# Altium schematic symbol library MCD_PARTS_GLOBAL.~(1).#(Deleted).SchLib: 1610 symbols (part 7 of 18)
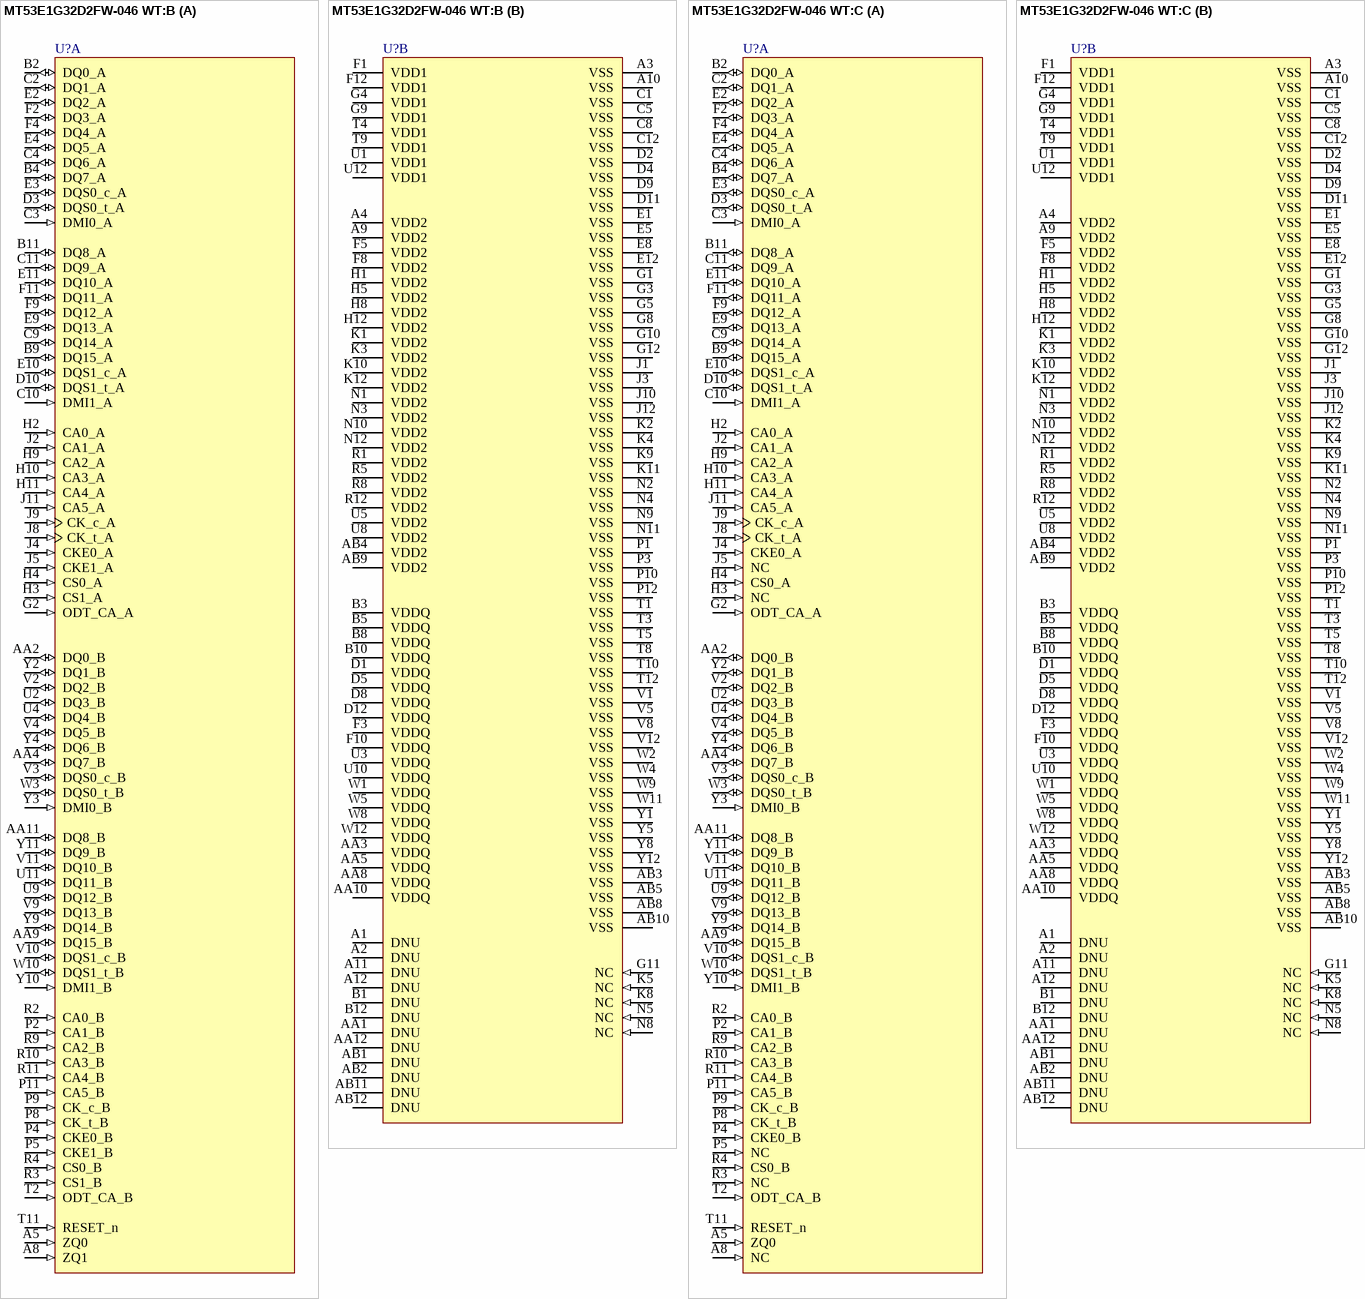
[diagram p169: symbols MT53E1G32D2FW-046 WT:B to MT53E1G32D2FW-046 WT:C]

## MT53E1G32D2FW-046 WT:C
designator U?
part A pins: A5 ZQ0 (in) "External impedance (240 ohm): This signal is used to calibrate the device output impedance.", A8 NC (in), AA2 DQ0_B (io) "Data input/output: Bidirectional data bus.", AA4 DQ7_B (io) "Data input/output: Bidirectional data bus.", AA9 DQ15_B (io) "Data input/output: Bidirectional data bus.", AA11 DQ8_B (io) "Data input/output: Bidirectional data bus.", B2 DQ0_A (io) "Data input/output: Bidirectional data bus.", B4 DQ7_A (io) "Data input/output: Bidirectional data bus.", B9 DQ15_A (io) "Data input/output: Bidirectional data bus.", B11 DQ8_A (io) "Data input/output: Bidirectional data bus.", C2 DQ1_A (io) "Data input/output: Bidirectional data bus.", C3 DMI0_A (in) "Input data mask: DM is an input mask signal for write data. Although DM ballsare input-only, the DM loading is designed to match that of DQ and DQS balls.DM[3:0] is DM for each of the four data bytes, respectively.", C4 DQ6_A (io) "Data input/output: Bidirectional data bus.", C9 DQ14_A (io) "Data input/output: Bidirectional data bus.", C10 DMI1_A (in) "Input data mask: DM is an input mask signal for write data. Although DM ballsare input-only, the DM loading is designed to match that of DQ and DQS balls.DM[3:0] is DM for each of the four data bytes, respectively.", C11 DQ9_A (io) "Data input/output: Bidirectional data bus.", D3 DQS0_t_A (io) "Data strobe: The data strobe is bidirectional (used for read and write data) andcomplementary (DQS and DQS#). It is edge-aligned output with read data andcentered input with write data. DQS[3:0]/DQS[3:0]# is DQS for each of (See Datasheet)", D10 DQS1_t_A (io) "Data strobe: The data strobe is bidirectional (used for read and write data) andcomplementary (DQS and DQS#). It is edge-aligned output with read data andcentered input with write data. DQS[3:0]/DQS[3:0]# is DQS for each of (See Datasheet)", E2 DQ2_A (io) "Data input/output: Bidirectional data bus.", E3 DQS0_c_A (io) "Data strobe: The data strobe is bidirectional (used for read and write data) andcomplementary (DQS and DQS#). It is edge-aligned output with read data andcentered input with write data. DQS[3:0]/DQS[3:0]# is DQS for each of (See Datasheet)", E4 DQ5_A (io) "Data input/output: Bidirectional data bus.", E9 DQ13_A (io) "Data input/output: Bidirectional data bus.", E10 DQS1_c_A (io) "Data strobe: The data strobe is bidirectional (used for read and write data) andcomplementary (DQS and DQS#). It is edge-aligned output with read data andcentered input with write data. DQS[3:0]/DQS[3:0]# is DQS for each of (See Datasheet)", E11 DQ10_A (io) "Data input/output: Bidirectional data bus.", F2 DQ3_A (io) "Data input/output: Bidirectional data bus.", F4 DQ4_A (io) "Data input/output: Bidirectional data bus.", F9 DQ12_A (io) "Data input/output: Bidirectional data bus.", F11 DQ11_A (io) "Data input/output: Bidirectional data bus.", G2 ODT_CA_A (in) "on die termination on CA", H2 CA0_A (in) "Command/address inputs: Provide the command and address inputs accordingto the command truth table.", H3 NC (in), H4 CS0_A (in) "Chip select: CS# is considered part of the command code and is sampled at therising edge of CK.", H9 CA2_A (in) "Command/address inputs: Provide the command and address inputs accordingto the command truth table.", H10 CA3_A (in) "Command/address inputs: Provide the command and address inputs accordingto the command truth table.", H11 CA4_A (in) "Command/address inputs: Provide the command and address inputs accordingto the command truth table.", J2 CA1_A (in) "Command/address inputs: Provide the command and address inputs accordingto the command truth table.", J4 CKE0_A (in) "Clock enable: CKE HIGH activates and CKE LOW deactivates the internal clocksignals, input buffers, and output drivers. Power-saving modes are entered andexited via CKE transitions. CKE is considered part of the command code. (See Datasheet)", J5 NC (in), J8 CK_t_A (in) "Clock: CK and CK# are differential clock inputs. All CA inputs are sampled onboth rising and falling edges of CK. CS and CKE inputs are sampled at the risingedge of CK. AC timings are referenced to clock.", J9 CK_c_A (in) "Clock: CK and CK# are differential clock inputs. All CA inputs are sampled onboth rising and falling edges of CK. CS and CKE inputs are sampled at the risingedge of CK. AC timings are referenced to clock.", J11 CA5_A (in) "Command/address inputs: Provide the command and address inputs accordingto the command truth table.", P2 CA1_B (in) "Command/address inputs: Provide the command and address inputs accordingto the command truth table.", P4 CKE0_B (in) "Clock enable: CKE HIGH activates and CKE LOW deactivates the internal clocksignals, input buffers, and output drivers. Power-saving modes are entered andexited via CKE transitions. CKE is considered part of the command code. (See Datasheet)", P5 NC (in), P8 CK_t_B (in) "Clock: CK and CK# are differential clock inputs. All CA inputs are sampled onboth rising and falling edges of CK. CS and CKE inputs are sampled at the risingedge of CK. AC timings are referenced to clock.", P9 CK_c_B (in) "Clock: CK and CK# are differential clock inputs. All CA inputs are sampled onboth rising and falling edges of CK. CS and CKE inputs are sampled at the risingedge of CK. AC timings are referenced to clock.", P11 CA5_B (in) "Command/address inputs: Provide the command and address inputs accordingto the command truth table.", R2 CA0_B (in) "Command/address inputs: Provide the command and address inputs accordingto the command truth table.", R3 NC (in), R4 CS0_B (in) "Chip select: CS# is considered part of the command code and is sampled at therising edge of CK.", R9 CA2_B (in) "Command/address inputs: Provide the command and address inputs accordingto the command truth table.", R10 CA3_B (in) "Command/address inputs: Provide the command and address inputs accordingto the command truth table.", R11 CA4_B (in) "Command/address inputs: Provide the command and address inputs accordingto the command truth table.", T2 ODT_CA_B (in) "on die termination on CA", T11 RESET_n (in) "Reset active low", U2 DQ3_B (io) "Data input/output: Bidirectional data bus.", U4 DQ4_B (io) "Data input/output: Bidirectional data bus.", U9 DQ12_B (io) "Data input/output: Bidirectional data bus.", U11 DQ11_B (io) "Data input/output: Bidirectional data bus.", V2 DQ2_B (io) "Data input/output: Bidirectional data bus.", V3 DQS0_c_B (io) "Data strobe: The data strobe is bidirectional (used for read and write data) andcomplementary (DQS and DQS#). It is edge-aligned output with read data andcentered input with write data. DQS[3:0]/DQS[3:0]# is DQS for each of (See Datasheet)", V4 DQ5_B (io) "Data input/output: Bidirectional data bus.", V9 DQ13_B (io) "Data input/output: Bidirectional data bus.", V10 DQS1_c_B (io) "Data strobe: The data strobe is bidirectional (used for read and write data) andcomplementary (DQS and DQS#). It is edge-aligned output with read data andcentered input with write data. DQS[3:0]/DQS[3:0]# is DQS for each of (See Datasheet)", V11 DQ10_B (io) "Data input/output: Bidirectional data bus.", W3 DQS0_t_B (io) "Data strobe: The data strobe is bidirectional (used for read and write data) andcomplementary (DQS and DQS#). It is edge-aligned output with read data andcentered input with write data. DQS[3:0]/DQS[3:0]# is DQS for each of (See Datasheet)", W10 DQS1_t_B (io) "Data strobe: The data strobe is bidirectional (used for read and write data) andcomplementary (DQS and DQS#). It is edge-aligned output with read data andcentered input with write data. DQS[3:0]/DQS[3:0]# is DQS for each of (See Datasheet)", Y2 DQ1_B (io) "Data input/output: Bidirectional data bus.", Y3 DMI0_B (in) "Input data mask: DM is an input mask signal for write data. Although DM ballsare input-only, the DM loading is designed to match that of DQ and DQS balls.DM[3:0] is DM for each of the four data bytes, respectively.", Y4 DQ6_B (io) "Data input/output: Bidirectional data bus.", Y9 DQ14_B (io) "Data input/output: Bidirectional data bus.", Y10 DMI1_B (in) "Input data mask: DM is an input mask signal for write data. Although DM ballsare input-only, the DM loading is designed to match that of DQ and DQS balls.DM[3:0] is DM for each of the four data bytes, respectively.", Y11 DQ9_B (io) "Data input/output: Bidirectional data bus."
part B pins: A1 DNU "Do not use: Must be grounded or left floating.", A2 DNU "Do not use: Must be grounded or left floating.", A3 VSS (power) "Common ground.", A4 VDD2 (power) "Core power: Supply 2.", A9 VDD2 (power) "Core power: Supply 2.", A10 VSS (power) "Common ground.", A11 DNU "Do not use: Must be grounded or left floating.", A12 DNU "Do not use: Must be grounded or left floating.", AA1 DNU "Do not use: Must be grounded or left floating.", AA3 VDDQ (power) "DQ power supply: Isolated on the die for improved noise immunity.", AA5 VDDQ (power) "DQ power supply: Isolated on the die for improved noise immunity.", AA8 VDDQ (power) "DQ power supply: Isolated on the die for improved noise immunity.", AA10 VDDQ (power) "DQ power supply: Isolated on the die for improved noise immunity.", AA12 DNU "Do not use: Must be grounded or left floating.", AB1 DNU "Do not use: Must be grounded or left floating.", AB2 DNU "Do not use: Must be grounded or left floating.", AB3 VSS "Common ground.", AB4 VDD2 (power) "Core power: Supply 2.", AB5 VSS "Common ground.", AB8 VSS "Common ground.", AB9 VDD2 (power) "Core power: Supply 2.", AB10 VSS "Common ground.", AB11 DNU "Do not use: Must be grounded or left floating.", AB12 DNU "Do not use: Must be grounded or left floating.", B1 DNU "Do not use: Must be grounded or left floating.", B3 VDDQ (power) "DQ power supply: Isolated on the die for improved noise immunity.", B5 VDDQ (power) "DQ power supply: Isolated on the die for improved noise immunity.", B8 VDDQ (power) "DQ power supply: Isolated on the die for improved noise immunity.", B10 VDDQ (power) "DQ power supply: Isolated on the die for improved noise immunity.", B12 DNU "Do not use: Must be grounded or left floating.", C1 VSS (power) "Common ground.", C5 VSS (power) "Common ground.", C8 VSS (power) "Common ground.", C12 VSS (power) "Common ground.", D1 VDDQ (power) "DQ power supply: Isolated on the die for improved noise immunity.", D2 VSS (power) "Common ground.", D4 VSS (power) "Common ground.", D5 VDDQ (power) "DQ power supply: Isolated on the die for improved noise immunity.", D8 VDDQ (power) "DQ power supply: Isolated on the die for improved noise immunity.", D9 VSS (power) "Common ground.", D11 VSS (power) "Common ground.", D12 VDDQ (power) "DQ power supply: Isolated on the die for improved noise immunity.", E1 VSS (power) "Common ground.", E5 VSS (power) "Common ground.", E8 VSS (power) "Common ground.", E12 VSS (power) "Common ground.", F1 VDD1 (power) "Core power: Supply 1.", F3 VDDQ (power) "DQ power supply: Isolated on the die for improved noise immunity.", F5 VDD2 (power) "Core power: Supply 2.", F8 VDD2 (power) "Core power: Supply 2.", F10 VDDQ (power) "DQ power supply: Isolated on the die for improved noise immunity.", F12 VDD1 (power) "Core power: Supply 1.", G1 VSS (power) "Common ground.", G3 VSS (power) "Common ground.", G4 VDD1 (power) "Core power: Supply 1.", G5 VSS (power) "Common ground.", G8 VSS (power) "Common ground.", G9 VDD1 (power) "Core power: Supply 1.", G10 VSS (power) "Common ground.", G11 NC (in) "Not connected", G12 VSS (power) "Common ground.", H1 VDD2 (power) "Core power: Supply 2.", H5 VDD2 (power) "Core power: Supply 2.", H8 VDD2 (power) "Core power: Supply 2.", H12 VDD2 (power) "Core power: Supply 2.", J1 VSS (power) "Common ground.", J3 VSS (power) "Common ground.", J10 VSS (power) "Common ground.", J12 VSS (power) "Common ground.", K1 VDD2 (power) "Core power: Supply 2.", K2 VSS (power) "Common ground.", K3 VDD2 (power) "Core power: Supply 2.", K4 VSS (power) "Common ground.", K5 NC (in) "Not connected", K8 NC (in) "Not connected", K9 VSS (power) "Common ground.", K10 VDD2 (power) "Core power: Supply 2.", K11 VSS "Common ground.", K12 VDD2 (power) "Core power: Supply 2.", N1 VDD2 (power) "Core power: Supply 2.", N2 VSS "Common ground.", N3 VDD2 (power) "Core power: Supply 2.", N4 VSS "Common ground.", N5 NC (in) "Not connected", N8 NC (in) "Not connected", N9 VSS "Common ground.", N10 VDD2 (power) "Core power: Supply 2.", N11 VSS "Common ground.", N12 VDD2 (power) "Core power: Supply 2.", P1 VSS "Common ground.", P3 VSS (power) "Common ground.", P10 VSS (power) "Common ground.", P12 VSS "Common ground.", R1 VDD2 (power) "Core power: Supply 2.", R5 VDD2 (power) "Core power: Supply 2.", R8 VDD2 (power) "Core power: Supply 2.", R12 VDD2 (power) "Core power: Supply 2.", T1 VSS "Common ground.", T3 VSS "Common ground.", T4 VDD1 (power) "Core power: Supply 1.", T5 VSS "Common ground.", T8 VSS "Common ground.", T9 VDD1 (power) "Core power: Supply 1.", T10 VSS "Common ground.", T12 VSS "Common ground.", U1 VDD1 (power) "Core power: Supply 1.", U3 VDDQ (power) "DQ power supply: Isolated on the die for improved noise immunity.", U5 VDD2 (power) "Core power: Supply 2.", U8 VDD2 (power) "Core power: Supply 2.", U10 VDDQ (power) "DQ power supply: Isolated on the die for improved noise immunity.", U12 VDD1 (power) "Core power: Supply 1.", V1 VSS (power) "Common ground.", V5 VSS (power) "Common ground.", V8 VSS "Common ground.", V12 VSS "Common ground.", W1 VDDQ (power) "DQ power supply: Isolated on the die for improved noise immunity.", W2 VSS "Common ground.", W4 VSS "Common ground.", W5 VDDQ (power) "DQ power supply: Isolated on the die for improved noise immunity.", W8 VDDQ (power) "DQ power supply: Isolated on the die for improved noise immunity.", W9 VSS "Common ground.", W11 VSS "Common ground.", W12 VDDQ (power) "DQ power supply: Isolated on the die for improved noise immunity.", Y1 VSS "Common ground.", Y5 VSS "Common ground.", Y8 VSS "Common ground.", Y12 VSS "Common ground."

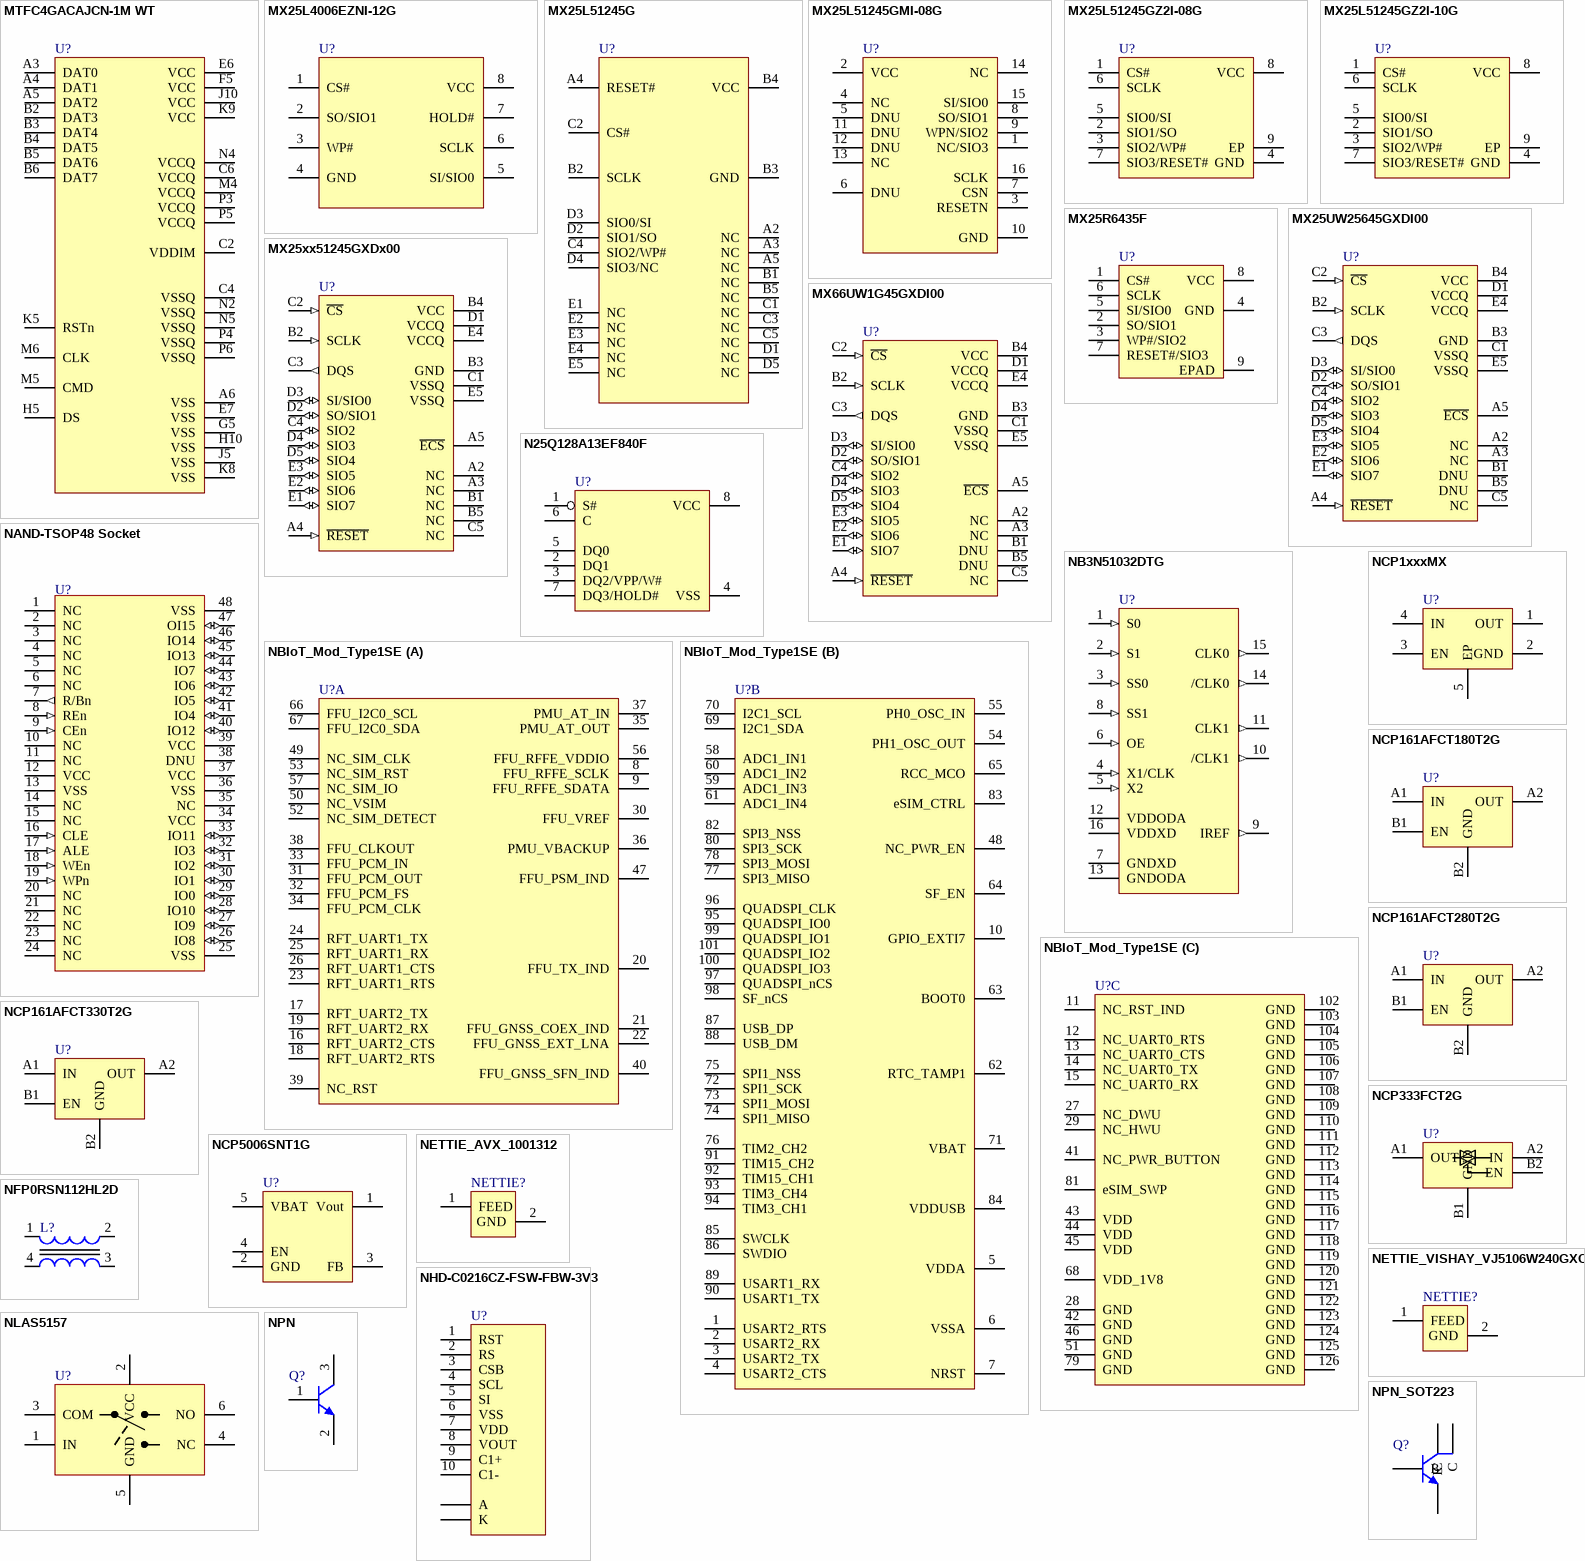
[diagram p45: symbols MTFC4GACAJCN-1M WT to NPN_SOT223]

## MTFC4GACAJCN-1M WT
designator U?
pins: A3 DAT0, A4 DAT1, A5 DAT2, A6 VSS, B2 DAT3, B3 DAT4, B4 DAT5, B5 DAT6, B6 DAT7, C2 VDDIM, C4 VSSQ, C6 VCCQ, E6 VCC, E7 VSS, F5 VCC, G5 VSS, H5 DS, H10 VSS, J5 VSS, J10 VCC, K5 RSTn, K8 VSS, K9 VCC, M4 VCCQ, M5 CMD, M6 CLK, N2 VSSQ, N4 VCCQ, N5 VSSQ, P3 VCCQ, P4 VSSQ, P5 VCCQ, P6 VSSQ

## MX25L4006EZNI-12G
designator U?
pins: 1 CS#, 2 SO/SIO1, 3 WP#, 4 GND, 5 SI/SIO0, 6 SCLK, 7 HOLD#, 8 VCC

## MX25L51245G
designator U?
pins: A2 NC, A3 NC, A4 RESET#, A5 NC, B1 NC, B2 SCLK, B3 GND, B4 VCC, B5 NC, C1 NC, C2 CS#, C3 NC, C4 SIO2/WP#, C5 NC, D1 NC, D2 SIO1/SO, D3 SIO0/SI, D4 SIO3/NC, D5 NC, E1 NC, E2 NC, E3 NC, E4 NC, E5 NC

## MX25L51245GMI-08G
designator U?
pins: 1 NC/SIO3, 2 VCC, 3 RESETN, 4 NC, 5 DNU, 6 DNU, 7 CSN, 8 SO/SIO1, 9 WPN/SIO2, 10 GND, 11 DNU, 12 DNU, 13 NC, 14 NC, 15 SI/SIO0, 16 SCLK

## MX25L51245GZ2I-08G
designator U?
pins: 1 CS#, 2 SIO1/SO, 3 SIO2/WP#, 4 GND, 5 SIO0/SI, 6 SCLK, 7 SIO3/RESET#, 8 VCC, 9 EP

## MX25L51245GZ2I-10G
designator U?
pins: 1 CS#, 2 SIO1/SO, 3 SIO2/WP#, 4 GND, 5 SIO0/SI, 6 SCLK, 7 SIO3/RESET#, 8 VCC, 9 EP

## MX25R6435F
designator U?
pins: 1 CS#, 2 SO/SIO1, 3 WP#/SIO2, 4 GND, 5 SI/SIO0, 6 SCLK, 7 RESET#/SIO3, 8 VCC, 9 EPAD

## MX25UW25645GXDI00
designator U?
pins: A2 NC, A3 NC, A4 ~{RESET} (in), A5 ~{ECS}, B1 DNU, B2 SCLK (in), B3 GND (power), B4 VCC (power), B5 DNU, C1 VSSQ (power), C2 ~{CS} (in), C3 DQS (out), C4 SIO2 (io), C5 NC, D1 VCCQ (power), D2 SO/SIO1 (io), D3 SI/SIO0 (io), D4 SIO3 (io), D5 SIO4 (io), E1 SIO7 (io), E2 SIO6 (io), E3 SIO5 (io), E4 VCCQ (power), E5 VSSQ (power)

## MX25xx51245GXDx00
designator U?
pins: A2 NC, A3 NC, A4 ~{RESET} (in), A5 ~{ECS}, B1 NC, B2 SCLK (in), B3 GND (power), B4 VCC (power), B5 NC, C1 VSSQ (power), C2 ~{CS} (in), C3 DQS (out), C4 SIO2 (io), C5 NC, D1 VCCQ (power), D2 SO/SIO1 (io), D3 SI/SIO0 (io), D4 SIO3 (io), D5 SIO4 (io), E1 SIO7 (io), E2 SIO6 (io), E3 SIO5 (io), E4 VCCQ (power), E5 VSSQ (power)
1 alternate drawing of the same symbol

## MX66UW1G45GXDI00
designator U?
pins: A2 NC, A3 NC, A4 ~{RESET} (in), A5 ~{ECS}, B1 DNU, B2 SCLK (in), B3 GND (power), B4 VCC (power), B5 DNU, C1 VSSQ (power), C2 ~{CS} (in), C3 DQS (out), C4 SIO2 (io), C5 NC, D1 VCCQ (power), D2 SO/SIO1 (io), D3 SI/SIO0 (io), D4 SIO3 (io), D5 SIO4 (io), E1 SIO7 (io), E2 SIO6 (io), E3 SIO5 (io), E4 VCCQ (power), E5 VSSQ (power)

## N25Q128A13EF840F
designator U?
pins: 1 S#, 2 DQ1, 3 DQ2/VPP/W#, 4 VSS, 5 DQ0, 6 C, 7 DQ3/HOLD#, 8 VCC

## NAND-TSOP48 Socket
designator U?
pins: 1 NC, 2 NC, 3 NC, 4 NC, 5 NC, 6 NC, 7 R/Bn (out), 8 REn (in), 9 CEn (in), 10 NC, 11 NC, 12 VCC, 13 VSS, 14 NC, 15 NC, 16 CLE (in), 17 ALE (in), 18 WEn (in), 19 WPn (in), 20 NC, 21 NC, 22 NC, 23 NC, 24 NC, 25 VSS, 26 IO8 (io), 27 IO9 (io), 28 IO10 (io), 29 IO0 (io), 30 IO1 (io), 31 IO2 (io), 32 IO3 (io), 33 IO11 (io), 34 VCC, 35 NC, 36 VSS, 37 VCC, 38 DNU, 39 VCC, 40 IO12 (io), 41 IO4 (io), 42 IO5 (io), 43 IO6 (io), 44 IO7 (io), 45 IO13 (io), 46 IO14 (io), 47 OI15 (io), 48 VSS

## NB3N51032DTG
designator U?
pins: 1 S0 (in) "Transmit Data Input", 2 S1 (in) "Slope-Control Input", 3 SS0 (in) "Receive Data Output", 4 X1/CLK (in), 5 X2 (in), 6 OE (in), 7 GNDXD, 8 SS1 (in), 9 IREF (out) "Ground", 10 /CLK1 (out) "Ground", 11 CLK1 (out) "Ground", 12 VDDODA (power), 13 GNDODA, 14 /CLK0 (out) "Ground", 15 CLK0 (out) "Ground", 16 VDDXD (power)

## NBIoT_Mod_Type1SE
designator U?
part A pins: 8 FFU_RFFE_SCLK, 9 FFU_RFFE_SDATA, 16 RFT_UART2_CTS, 17 RFT_UART2_TX, 18 RFT_UART2_RTS, 19 RFT_UART2_RX, 20 FFU_TX_IND, 21 FFU_GNSS_COEX_IND, 22 FFU_GNSS_EXT_LNA, 23 RFT_UART1_RTS, 24 RFT_UART1_TX, 25 RFT_UART1_RX, 26 RFT_UART1_CTS, 30 FFU_VREF, 31 FFU_PCM_OUT, 32 FFU_PCM_FS, 33 FFU_PCM_IN, 34 FFU_PCM_CLK, 35 PMU_AT_OUT, 36 PMU_VBACKUP, 37 PMU_AT_IN, 38 FFU_CLKOUT, 39 NC_RST, 40 FFU_GNSS_SFN_IND, 47 FFU_PSM_IND, 49 NC_SIM_CLK, 50 NC_VSIM, 52 NC_SIM_DETECT, 53 NC_SIM_RST, 56 FFU_RFFE_VDDIO, 57 NC_SIM_IO, 66 FFU_I2C0_SCL, 67 FFU_I2C0_SDA
part B pins: 1 USART2_RTS, 2 USART2_RX, 3 USART2_TX, 4 USART2_CTS, 5 VDDA, 6 VSSA, 7 NRST, 10 GPIO_EXTI7, 48 NC_PWR_EN, 54 PH1_OSC_OUT, 55 PH0_OSC_IN, 58 ADC1_IN1, 59 ADC1_IN3, 60 ADC1_IN2, 61 ADC1_IN4, 62 RTC_TAMP1, 63 BOOT0, 64 SF_EN, 65 RCC_MCO, 69 I2C1_SDA, 70 I2C1_SCL, 71 VBAT, 72 SPI1_SCK, 73 SPI1_MOSI, 74 SPI1_MISO, 75 SPI1_NSS, 76 TIM2_CH2, 77 SPI3_MISO, 78 SPI3_MOSI, 80 SPI3_SCK, 82 SPI3_NSS, 83 eSIM_CTRL, 84 VDDUSB, 85 SWCLK, 86 SWDIO, 87 USB_DP, 88 USB_DM, 89 USART1_RX, 90 USART1_TX, 91 TIM15_CH2, 92 TIM15_CH1, 93 TIM3_CH4, 94 TIM3_CH1, 95 QUADSPI_IO0, 96 QUADSPI_CLK, 97 QUADSPI_nCS, 98 SF_nCS, 99 QUADSPI_IO1, 100 QUADSPI_IO3, 101 QUADSPI_IO2
part C pins: 11 NC_RST_IND, 12 NC_UART0_RTS, 13 NC_UART0_CTS, 14 NC_UART0_TX, 15 NC_UART0_RX, 27 NC_DWU, 28 GND, 29 NC_HWU, 41 NC_PWR_BUTTON, 42 GND, 43 VDD, 44 VDD, 45 VDD, 46 GND, 51 GND, 68 VDD_1V8, 79 GND, 81 eSIM_SWP, 102 GND, 103 GND, 104 GND, 105 GND, 106 GND, 107 GND, 108 GND, 109 GND, 110 GND, 111 GND, 112 GND, 113 GND, 114 GND, 115 GND, 116 GND, 117 GND, 118 GND, 119 GND, 120 GND, 121 GND, 122 GND, 123 GND, 124 GND, 125 GND, 126 GND

## NCP1xxxMX
designator U?
pins: 1 OUT, 2 GND, 3 EN, 4 IN, 5 EP

## NCP161AFCT180T2G
designator U?
pins: A1 IN, A2 OUT, B1 EN, B2 GND

## NCP161AFCT280T2G
designator U?
pins: A1 IN, A2 OUT, B1 EN, B2 GND

## NCP161AFCT330T2G
designator U?
pins: A1 IN, A2 OUT, B1 EN, B2 GND

## NCP333FCT2G
designator U?
pins: A1 OUT, A2 IN, B1 GND, B2 EN

## NCP5006SNT1G
designator U?
pins: 1 Vout, 2 GND, 3 FB, 4 EN, 5 VBAT

## NETTIE_AVX_1001312
designator NETTIE?  (net tie, no BOM)
pins: 1 FEED, 2 GND

## NETTIE_VISHAY_VJ5106W240GXCMT
designator NETTIE?
pins: 1 FEED, 2 GND

## NFP0RSN112HL2D
designator L?
pins: 1, 2, 3, 4

## NHD-C0216CZ-FSW-FBW-3V3
designator U?
pins: 1 RST, 2 RS, 3 CSB, 4 SCL, 5 SI, 6 VSS, 7 VDD, 8 VOUT, 9 C1+, 10 C1-, 11 A, 12 K

## NLAS5157
designator U?
pins: 1 IN, 2 VCC, 3 COM, 4 NC, 5 GND, 6 NO

## NPN
designator Q?
pins: 1 B, 2 E, 3 C

## NPN_SOT223
designator Q?
pins: 1 B, 2 C, 3 E, 4 C

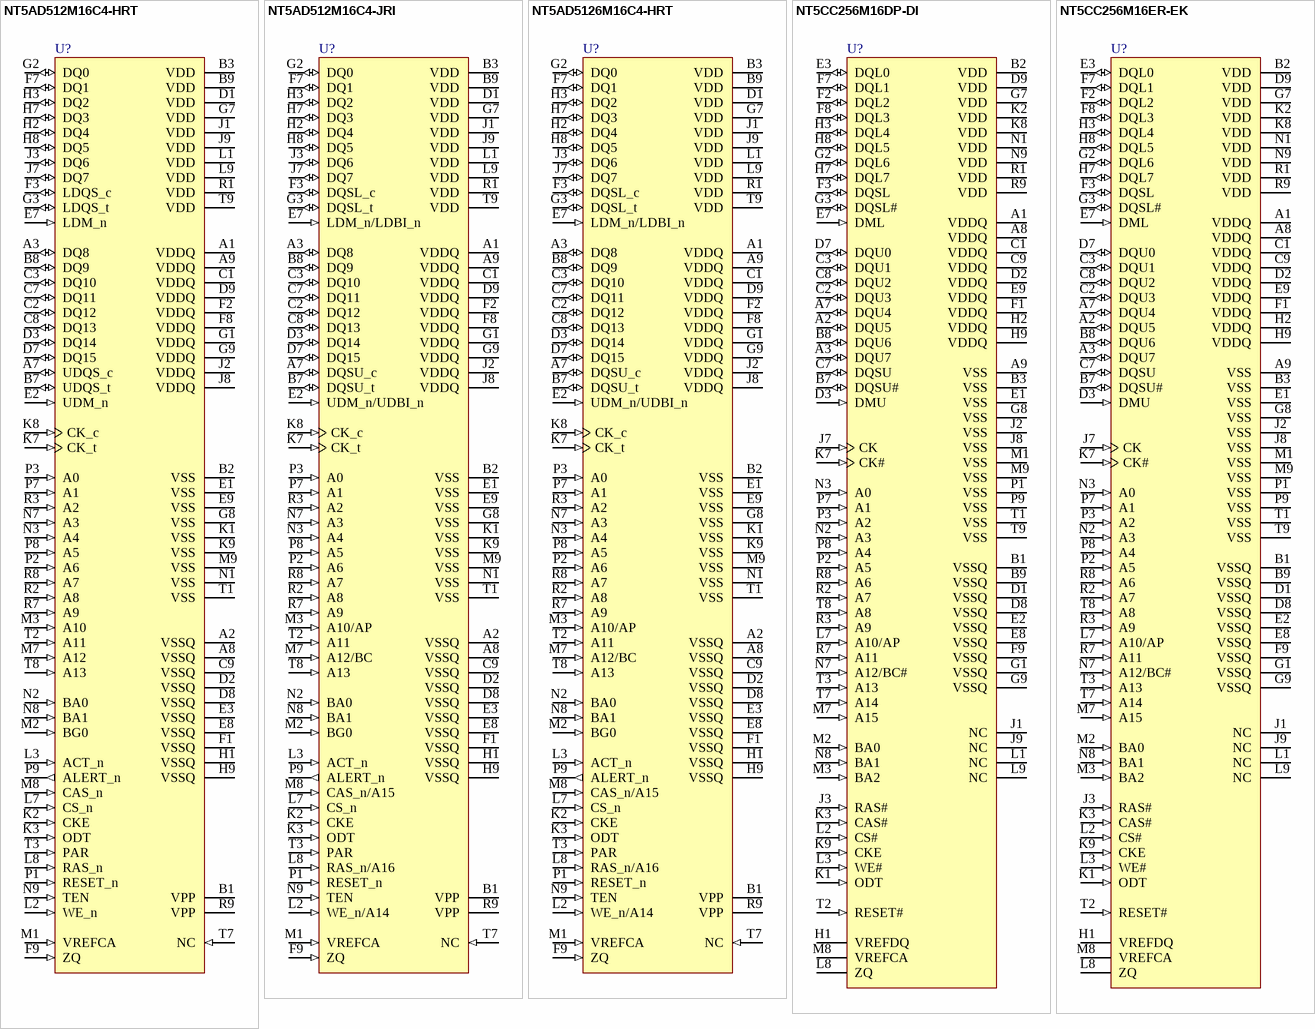
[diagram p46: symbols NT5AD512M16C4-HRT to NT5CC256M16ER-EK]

## NT5AD512M16C4-HRT
designator U?
pins: A1 VDDQ (power) "DQ power supply: Isolated on the die for improved noise immunity.", A2 VSSQ (power) "DQ ground.", A3 DQ8 (io) "Data input/output: Bidirectional data bus.", A7 UDQS_c (io) "Data strobe: The data strobe is bidirectional (used for read and write data) andcomplementary (DQS and DQS#). It is edge-aligned output with read data andcentered input with write data. DQS[3:0]/DQS[3:0]# is DQS for each of (See Datasheet)", A8 VSSQ (power) "DQ ground.", A9 VDDQ (power) "DQ power supply: Isolated on the die for improved noise immunity.", B1 VPP (power) "DRAM activating power supply", B2 VSS (power) "Common ground.", B3 VDD (power) "Power supply", B7 UDQS_t (io) "Data strobe: The data strobe is bidirectional (used for read and write data) andcomplementary (DQS and DQS#). It is edge-aligned output with read data andcentered input with write data. DQS[3:0]/DQS[3:0]# is DQS for each of (See Datasheet)", B8 DQ9 (io) "Data input/output: Bidirectional data bus.", B9 VDD (power) "Power supply", C1 VDDQ (power) "DQ power supply: Isolated on the die for improved noise immunity.", C2 DQ12 (io) "Data input/output: Bidirectional data bus.", C3 DQ10 (io) "Data input/output: Bidirectional data bus.", C7 DQ11 (io) "Data input/output: Bidirectional data bus.", C8 DQ13 (io) "Data input/output: Bidirectional data bus.", C9 VSSQ (power) "DQ ground.", D1 VDD (power) "Power supply", D2 VSSQ (power) "DQ ground.", D3 DQ14 (io) "Data input/output: Bidirectional data bus.", D7 DQ15 (io) "Data input/output: Bidirectional data bus.", D8 VSSQ (power) "DQ ground.", D9 VDDQ (power) "DQ power supply: Isolated on the die for improved noise immunity.", E1 VSS (power) "Common ground.", E2 UDM_n (in) "Input data mask: DM is an input mask signal for write data. Although DM ballsare input-only, the DM loading is designed to match that of DQ and DQS balls.DM[3:0] is DM for each of the four data bytes, respectively.", E3 VSSQ (power) "DQ ground.", E7 LDM_n (in) "Input data mask: DM is an input mask signal for write data. Although DM ballsare input-only, the DM loading is designed to match that of DQ and DQS balls.DM[3:0] is DM for each of the four data bytes, respectively.", E8 VSSQ (power) "DQ ground.", E9 VSS (power) "Common ground.", F1 VSSQ (power) "DQ ground.", F2 VDDQ (power) "DQ power supply: Isolated on the die for improved noise immunity.", F3 LDQS_c (io) "Data strobe: The data strobe is bidirectional (used for read and write data) andcomplementary (DQS and DQS#). It is edge-aligned output with read data andcentered input with write data. DQS[3:0]/DQS[3:0]# is DQS for each of (See Datasheet)", F7 DQ1 (io) "Data input/output: Bidirectional data bus.", F8 VDDQ (power) "DQ power supply: Isolated on the die for improved noise immunity.", F9 ZQ (in) "External impedance (240 ohm): This signal is used to calibrate the device output impedance.", G1 VDDQ (power) "DQ power supply: Isolated on the die for improved noise immunity.", G2 DQ0 (io) "Data input/output: Bidirectional data bus.", G3 LDQS_t (io) "Data strobe: The data strobe is bidirectional (used for read and write data) andcomplementary (DQS and DQS#). It is edge-aligned output with read data andcentered input with write data. DQS[3:0]/DQS[3:0]# is DQS for each of (See Datasheet)", G7 VDD (power) "Power supply", G8 VSS (power) "Common ground.", G9 VDDQ (power) "DQ power supply: Isolated on the die for improved noise immunity.", H1 VSSQ (power) "DQ ground.", H2 DQ4 (io) "Data input/output: Bidirectional data bus.", H3 DQ2 (io) "Data input/output: Bidirectional data bus.", H7 DQ3 (io) "Data input/output: Bidirectional data bus.", H8 DQ5 (io) "Data input/output: Bidirectional data bus.", H9 VSSQ (power) "DQ ground.", J1 VDD (power) "Power supply", J2 VDDQ (power) "DQ power supply: Isolated on the die for improved noise immunity.", J3 DQ6 (io) "Data input/output: Bidirectional data bus.", J7 DQ7 (io) "Data input/output: Bidirectional data bus.", J8 VDDQ (power) "DQ power supply: Isolated on the die for improved noise immunity.", J9 VDD (power) "Power supply", K1 VSS (power) "Common ground.", K2 CKE (in) "Clock enable: CKE HIGH activates and CKE LOW deactivates the internal clocksignals, input buffers, and output drivers. Power-saving modes are entered andexited via CKE transitions. CKE is considered part of the command code. (See Datasheet)", K3 ODT (in) "on die termination on data, data strobe and data mask", K7 CK_t (in) "Clock: CK and CK# are differential clock inputs. All CA inputs are sampled onboth rising and falling edges of CK. CS and CKE inputs are sampled at the risingedge of CK. AC timings are referenced to clock.", K8 CK_c (in) "Clock: CK and CK# are differential clock inputs. All CA inputs are sampled onboth rising and falling edges of CK. CS and CKE inputs are sampled at the risingedge of CK. AC timings are referenced to clock.", K9 VSS (power) "Common ground.", L1 VDD (power) "Power supply", L2 WE_n (in) "Command/address inputs: Provide the command and address inputs accordingto the command truth table.", L3 ACT_n (in) "Command/address inputs: Provide the command and address inputs accordingto the command truth table.", L7 CS_n (in) "Chip select: CS# is considered part of the command code and is sampled at therising edge of CK.", L8 RAS_n (in) "Command/address inputs: Provide the command and address inputs accordingto the command truth table.", L9 VDD (power) "Power supply", M1 VREFCA (in) "Reference voltage for control, command and address pins", M2 BG0 (in) "Command/address inputs: Provide the command and address inputs accordingto the command truth table.", M3 A10 (in) "Command/address inputs: Provide the command and address inputs accordingto the command truth table.", M7 A12 (in) "Command/address inputs: Provide the command and address inputs accordingto the command truth table.", M8 CAS_n (in) "Command/address inputs: Provide the command and address inputs accordingto the command truth table.", M9 VSS (power) "Common ground.", N1 VSS (power) "Common ground.", N2 BA0 (in) "Command/address inputs: Provide the command and address inputs accordingto the command truth table.", N3 A4 (in) "Command/address inputs: Provide the command and address inputs accordingto the command truth table.", N7 A3 (in) "Command/address inputs: Provide the command and address inputs accordingto the command truth table.", N8 BA1 (in) "Command/address inputs: Provide the command and address inputs accordingto the command truth table.", N9 TEN (in) "Connectivity test mode", P1 RESET_n (in) "Reset active low", P2 A6 (in) "Command/address inputs: Provide the command and address inputs accordingto the command truth table.", P3 A0 (in) "Command/address inputs: Provide the command and address inputs accordingto the command truth table.", P7 A1 (in) "Command/address inputs: Provide the command and address inputs accordingto the command truth table.", P8 A5 (in) "Command/address inputs: Provide the command and address inputs accordingto the command truth table.", P9 ALERT_n (out) "Alert the controller that a specific even has occurred", R1 VDD (power) "Power supply", R2 A8 (in) "Command/address inputs: Provide the command and address inputs accordingto the command truth table.", R3 A2 (in) "Command/address inputs: Provide the command and address inputs accordingto the command truth table.", R7 A9 (in) "Command/address inputs: Provide the command and address inputs accordingto the command truth table.", R8 A7 (in) "Command/address inputs: Provide the command and address inputs accordingto the command truth table.", R9 VPP (power) "DRAM activating power supply", T1 VSS (power) "Common ground.", T2 A11 (in) "Command/address inputs: Provide the command and address inputs accordingto the command truth table.", T3 PAR (in) "Parity for command and address", T7 NC (in) "Not connected", T8 A13 (in) "Command/address inputs: Provide the command and address inputs accordingto the command truth table.", T9 VDD (power) "Power supply"

## NT5AD512M16C4-JRI
designator U?
pins: A1 VDDQ (power) "DQ power supply: Isolated on the die for improved noise immunity.", A2 VSSQ (power) "DQ ground.", A3 DQ8 (io) "Data input/output: Bidirectional data bus.", A7 DQSU_c (io) "Data strobe: The data strobe is bidirectional (used for read and write data) andcomplementary (DQS and DQS#). It is edge-aligned output with read data andcentered input with write data. DQS[3:0]/DQS[3:0]# is DQS for each of (See Datasheet)", A8 VSSQ (power) "DQ ground.", A9 VDDQ (power) "DQ power supply: Isolated on the die for improved noise immunity.", B1 VPP (power) "DRAM activating power supply", B2 VSS (power) "Common ground.", B3 VDD (power) "Power supply", B7 DQSU_t (io) "Data strobe: The data strobe is bidirectional (used for read and write data) andcomplementary (DQS and DQS#). It is edge-aligned output with read data andcentered input with write data. DQS[3:0]/DQS[3:0]# is DQS for each of (See Datasheet)", B8 DQ9 (io) "Data input/output: Bidirectional data bus.", B9 VDD (power) "Power supply", C1 VDDQ (power) "DQ power supply: Isolated on the die for improved noise immunity.", C2 DQ12 (io) "Data input/output: Bidirectional data bus.", C3 DQ10 (io) "Data input/output: Bidirectional data bus.", C7 DQ11 (io) "Data input/output: Bidirectional data bus.", C8 DQ13 (io) "Data input/output: Bidirectional data bus.", C9 VSSQ (power) "DQ ground.", D1 VDD (power) "Power supply", D2 VSSQ (power) "DQ ground.", D3 DQ14 (io) "Data input/output: Bidirectional data bus.", D7 DQ15 (io) "Data input/output: Bidirectional data bus.", D8 VSSQ (power) "DQ ground.", D9 VDDQ (power) "DQ power supply: Isolated on the die for improved noise immunity.", E1 VSS (power) "Common ground.", E2 UDM_n/UDBI_n (in) "Input data mask: DM is an input mask signal for write data. Although DM ballsare input-only, the DM loading is designed to match that of DQ and DQS balls.DM[3:0] is DM for each of the four data bytes, respectively.", E3 VSSQ (power) "DQ ground.", E7 LDM_n/LDBI_n (in) "Input data mask: DM is an input mask signal for write data. Although DM ballsare input-only, the DM loading is designed to match that of DQ and DQS balls.DM[3:0] is DM for each of the four data bytes, respectively.", E8 VSSQ (power) "DQ ground.", E9 VSS (power) "Common ground.", F1 VSSQ (power) "DQ ground.", F2 VDDQ (power) "DQ power supply: Isolated on the die for improved noise immunity.", F3 DQSL_c (io) "Data strobe: The data strobe is bidirectional (used for read and write data) andcomplementary (DQS and DQS#). It is edge-aligned output with read data andcentered input with write data. DQS[3:0]/DQS[3:0]# is DQS for each of (See Datasheet)", F7 DQ1 (io) "Data input/output: Bidirectional data bus.", F8 VDDQ (power) "DQ power supply: Isolated on the die for improved noise immunity.", F9 ZQ (in) "External impedance (240 ohm): This signal is used to calibrate the device output impedance.", G1 VDDQ (power) "DQ power supply: Isolated on the die for improved noise immunity.", G2 DQ0 (io) "Data input/output: Bidirectional data bus.", G3 DQSL_t (io) "Data strobe: The data strobe is bidirectional (used for read and write data) andcomplementary (DQS and DQS#). It is edge-aligned output with read data andcentered input with write data. DQS[3:0]/DQS[3:0]# is DQS for each of (See Datasheet)", G7 VDD (power) "Power supply", G8 VSS (power) "Common ground.", G9 VDDQ (power) "DQ power supply: Isolated on the die for improved noise immunity.", H1 VSSQ (power) "DQ ground.", H2 DQ4 (io) "Data input/output: Bidirectional data bus.", H3 DQ2 (io) "Data input/output: Bidirectional data bus.", H7 DQ3 (io) "Data input/output: Bidirectional data bus.", H8 DQ5 (io) "Data input/output: Bidirectional data bus.", H9 VSSQ (power) "DQ ground.", J1 VDD (power) "Power supply", J2 VDDQ (power) "DQ power supply: Isolated on the die for improved noise immunity.", J3 DQ6 (io) "Data input/output: Bidirectional data bus.", J7 DQ7 (io) "Data input/output: Bidirectional data bus.", J8 VDDQ (power) "DQ power supply: Isolated on the die for improved noise immunity.", J9 VDD (power) "Power supply", K1 VSS (power) "Common ground.", K2 CKE (in) "Clock enable: CKE HIGH activates and CKE LOW deactivates the internal clocksignals, input buffers, and output drivers. Power-saving modes are entered andexited via CKE transitions. CKE is considered part of the command code. (See Datasheet)", K3 ODT (in) "on die termination on data, data strobe and data mask", K7 CK_t (in) "Clock: CK and CK# are differential clock inputs. All CA inputs are sampled onboth rising and falling edges of CK. CS and CKE inputs are sampled at the risingedge of CK. AC timings are referenced to clock.", K8 CK_c (in) "Clock: CK and CK# are differential clock inputs. All CA inputs are sampled onboth rising and falling edges of CK. CS and CKE inputs are sampled at the risingedge of CK. AC timings are referenced to clock.", K9 VSS (power) "Common ground.", L1 VDD (power) "Power supply", L2 WE_n/A14 (in) "Command/address inputs: Provide the command and address inputs accordingto the command truth table.", L3 ACT_n (in) "Command/address inputs: Provide the command and address inputs accordingto the command truth table.", L7 CS_n (in) "Chip select: CS# is considered part of the command code and is sampled at therising edge of CK.", L8 RAS_n/A16 (in) "Command/address inputs: Provide the command and address inputs accordingto the command truth table.", L9 VDD (power) "Power supply", M1 VREFCA (in) "Reference voltage for control, command and address pins", M2 BG0 (in) "Command/address inputs: Provide the command and address inputs accordingto the command truth table.", M3 A10/AP (in) "Command/address inputs: Provide the command and address inputs accordingto the command truth table.", M7 A12/BC (in) "Command/address inputs: Provide the command and address inputs accordingto the command truth table.", M8 CAS_n/A15 (in) "Command/address inputs: Provide the command and address inputs accordingto the command truth table.", M9 VSS (power) "Common ground.", N1 VSS (power) "Common ground.", N2 BA0 (in) "Command/address inputs: Provide the command and address inputs accordingto the command truth table.", N3 A4 (in) "Command/address inputs: Provide the command and address inputs accordingto the command truth table.", N7 A3 (in) "Command/address inputs: Provide the command and address inputs accordingto the command truth table.", N8 BA1 (in) "Command/address inputs: Provide the command and address inputs accordingto the command truth table.", N9 TEN (in) "Connectivity test mode", P1 RESET_n (in) "Reset active low", P2 A6 (in) "Command/address inputs: Provide the command and address inputs accordingto the command truth table.", P3 A0 (in) "Command/address inputs: Provide the command and address inputs accordingto the command truth table.", P7 A1 (in) "Command/address inputs: Provide the command and address inputs accordingto the command truth table.", P8 A5 (in) "Command/address inputs: Provide the command and address inputs accordingto the command truth table.", P9 ALERT_n (out) "Alert the controller that a specific even has occurred", R1 VDD (power) "Power supply", R2 A8 (in) "Command/address inputs: Provide the command and address inputs accordingto the command truth table.", R3 A2 (in) "Command/address inputs: Provide the command and address inputs accordingto the command truth table.", R7 A9 (in) "Command/address inputs: Provide the command and address inputs accordingto the command truth table.", R8 A7 (in) "Command/address inputs: Provide the command and address inputs accordingto the command truth table.", R9 VPP (power) "DRAM activating power supply", T1 VSS (power) "Common ground.", T2 A11 (in) "Command/address inputs: Provide the command and address inputs accordingto the command truth table.", T3 PAR (in) "Parity for command and address", T7 NC (in) "Not connected", T8 A13 (in) "Command/address inputs: Provide the command and address inputs accordingto the command truth table.", T9 VDD (power) "Power supply"

## NT5AD5126M16C4-HRT
designator U?
pins: A1 VDDQ (power) "DQ power supply: Isolated on the die for improved noise immunity.", A2 VSSQ (power) "DQ ground.", A3 DQ8 (io) "Data input/output: Bidirectional data bus.", A7 DQSU_c (io) "Data strobe: The data strobe is bidirectional (used for read and write data) andcomplementary (DQS and DQS#). It is edge-aligned output with read data andcentered input with write data. DQS[3:0]/DQS[3:0]# is DQS for each of (See Datasheet)", A8 VSSQ (power) "DQ ground.", A9 VDDQ (power) "DQ power supply: Isolated on the die for improved noise immunity.", B1 VPP (power) "DRAM activating power supply", B2 VSS (power) "Common ground.", B3 VDD (power) "Power supply", B7 DQSU_t (io) "Data strobe: The data strobe is bidirectional (used for read and write data) andcomplementary (DQS and DQS#). It is edge-aligned output with read data andcentered input with write data. DQS[3:0]/DQS[3:0]# is DQS for each of (See Datasheet)", B8 DQ9 (io) "Data input/output: Bidirectional data bus.", B9 VDD (power) "Power supply", C1 VDDQ (power) "DQ power supply: Isolated on the die for improved noise immunity.", C2 DQ12 (io) "Data input/output: Bidirectional data bus.", C3 DQ10 (io) "Data input/output: Bidirectional data bus.", C7 DQ11 (io) "Data input/output: Bidirectional data bus.", C8 DQ13 (io) "Data input/output: Bidirectional data bus.", C9 VSSQ (power) "DQ ground.", D1 VDD (power) "Power supply", D2 VSSQ (power) "DQ ground.", D3 DQ14 (io) "Data input/output: Bidirectional data bus.", D7 DQ15 (io) "Data input/output: Bidirectional data bus.", D8 VSSQ (power) "DQ ground.", D9 VDDQ (power) "DQ power supply: Isolated on the die for improved noise immunity.", E1 VSS (power) "Common ground.", E2 UDM_n/UDBI_n (in) "Input data mask: DM is an input mask signal for write data. Although DM ballsare input-only, the DM loading is designed to match that of DQ and DQS balls.DM[3:0] is DM for each of the four data bytes, respectively.", E3 VSSQ (power) "DQ ground.", E7 LDM_n/LDBI_n (in) "Input data mask: DM is an input mask signal for write data. Although DM ballsare input-only, the DM loading is designed to match that of DQ and DQS balls.DM[3:0] is DM for each of the four data bytes, respectively.", E8 VSSQ (power) "DQ ground.", E9 VSS (power) "Common ground.", F1 VSSQ (power) "DQ ground.", F2 VDDQ (power) "DQ power supply: Isolated on the die for improved noise immunity.", F3 DQSL_c (io) "Data strobe: The data strobe is bidirectional (used for read and write data) andcomplementary (DQS and DQS#). It is edge-aligned output with read data andcentered input with write data. DQS[3:0]/DQS[3:0]# is DQS for each of (See Datasheet)", F7 DQ1 (io) "Data input/output: Bidirectional data bus.", F8 VDDQ (power) "DQ power supply: Isolated on the die for improved noise immunity.", F9 ZQ (in) "External impedance (240 ohm): This signal is used to calibrate the device output impedance.", G1 VDDQ (power) "DQ power supply: Isolated on the die for improved noise immunity.", G2 DQ0 (io) "Data input/output: Bidirectional data bus.", G3 DQSL_t (io) "Data strobe: The data strobe is bidirectional (used for read and write data) andcomplementary (DQS and DQS#). It is edge-aligned output with read data andcentered input with write data. DQS[3:0]/DQS[3:0]# is DQS for each of (See Datasheet)", G7 VDD (power) "Power supply", G8 VSS (power) "Common ground.", G9 VDDQ (power) "DQ power supply: Isolated on the die for improved noise immunity.", H1 VSSQ (power) "DQ ground.", H2 DQ4 (io) "Data input/output: Bidirectional data bus.", H3 DQ2 (io) "Data input/output: Bidirectional data bus.", H7 DQ3 (io) "Data input/output: Bidirectional data bus.", H8 DQ5 (io) "Data input/output: Bidirectional data bus.", H9 VSSQ (power) "DQ ground.", J1 VDD (power) "Power supply", J2 VDDQ (power) "DQ power supply: Isolated on the die for improved noise immunity.", J3 DQ6 (io) "Data input/output: Bidirectional data bus.", J7 DQ7 (io) "Data input/output: Bidirectional data bus.", J8 VDDQ (power) "DQ power supply: Isolated on the die for improved noise immunity.", J9 VDD (power) "Power supply", K1 VSS (power) "Common ground.", K2 CKE (in) "Clock enable: CKE HIGH activates and CKE LOW deactivates the internal clocksignals, input buffers, and output drivers. Power-saving modes are entered andexited via CKE transitions. CKE is considered part of the command code. (See Datasheet)", K3 ODT (in) "on die termination on data, data strobe and data mask", K7 CK_t (in) "Clock: CK and CK# are differential clock inputs. All CA inputs are sampled onboth rising and falling edges of CK. CS and CKE inputs are sampled at the risingedge of CK. AC timings are referenced to clock.", K8 CK_c (in) "Clock: CK and CK# are differential clock inputs. All CA inputs are sampled onboth rising and falling edges of CK. CS and CKE inputs are sampled at the risingedge of CK. AC timings are referenced to clock.", K9 VSS (power) "Common ground.", L1 VDD (power) "Power supply", L2 WE_n/A14 (in) "Command/address inputs: Provide the command and address inputs accordingto the command truth table.", L3 ACT_n (in) "Command/address inputs: Provide the command and address inputs accordingto the command truth table.", L7 CS_n (in) "Chip select: CS# is considered part of the command code and is sampled at therising edge of CK.", L8 RAS_n/A16 (in) "Command/address inputs: Provide the command and address inputs accordingto the command truth table.", L9 VDD (power) "Power supply", M1 VREFCA (in) "Reference voltage for control, command and address pins", M2 BG0 (in) "Command/address inputs: Provide the command and address inputs accordingto the command truth table.", M3 A10/AP (in) "Command/address inputs: Provide the command and address inputs accordingto the command truth table.", M7 A12/BC (in) "Command/address inputs: Provide the command and address inputs accordingto the command truth table.", M8 CAS_n/A15 (in) "Command/address inputs: Provide the command and address inputs accordingto the command truth table.", M9 VSS (power) "Common ground.", N1 VSS (power) "Common ground.", N2 BA0 (in) "Command/address inputs: Provide the command and address inputs accordingto the command truth table.", N3 A4 (in) "Command/address inputs: Provide the command and address inputs accordingto the command truth table.", N7 A3 (in) "Command/address inputs: Provide the command and address inputs accordingto the command truth table.", N8 BA1 (in) "Command/address inputs: Provide the command and address inputs accordingto the command truth table.", N9 TEN (in) "Connectivity test mode", P1 RESET_n (in) "Reset active low", P2 A6 (in) "Command/address inputs: Provide the command and address inputs accordingto the command truth table.", P3 A0 (in) "Command/address inputs: Provide the command and address inputs accordingto the command truth table.", P7 A1 (in) "Command/address inputs: Provide the command and address inputs accordingto the command truth table.", P8 A5 (in) "Command/address inputs: Provide the command and address inputs accordingto the command truth table.", P9 ALERT_n (out) "Alert the controller that a specific even has occurred", R1 VDD (power) "Power supply", R2 A8 (in) "Command/address inputs: Provide the command and address inputs accordingto the command truth table.", R3 A2 (in) "Command/address inputs: Provide the command and address inputs accordingto the command truth table.", R7 A9 (in) "Command/address inputs: Provide the command and address inputs accordingto the command truth table.", R8 A7 (in) "Command/address inputs: Provide the command and address inputs accordingto the command truth table.", R9 VPP (power) "DRAM activating power supply", T1 VSS (power) "Common ground.", T2 A11 (in) "Command/address inputs: Provide the command and address inputs accordingto the command truth table.", T3 PAR (in) "Parity for command and address", T7 NC (in) "Not connected", T8 A13 (in) "Command/address inputs: Provide the command and address inputs accordingto the command truth table.", T9 VDD (power) "Power supply"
